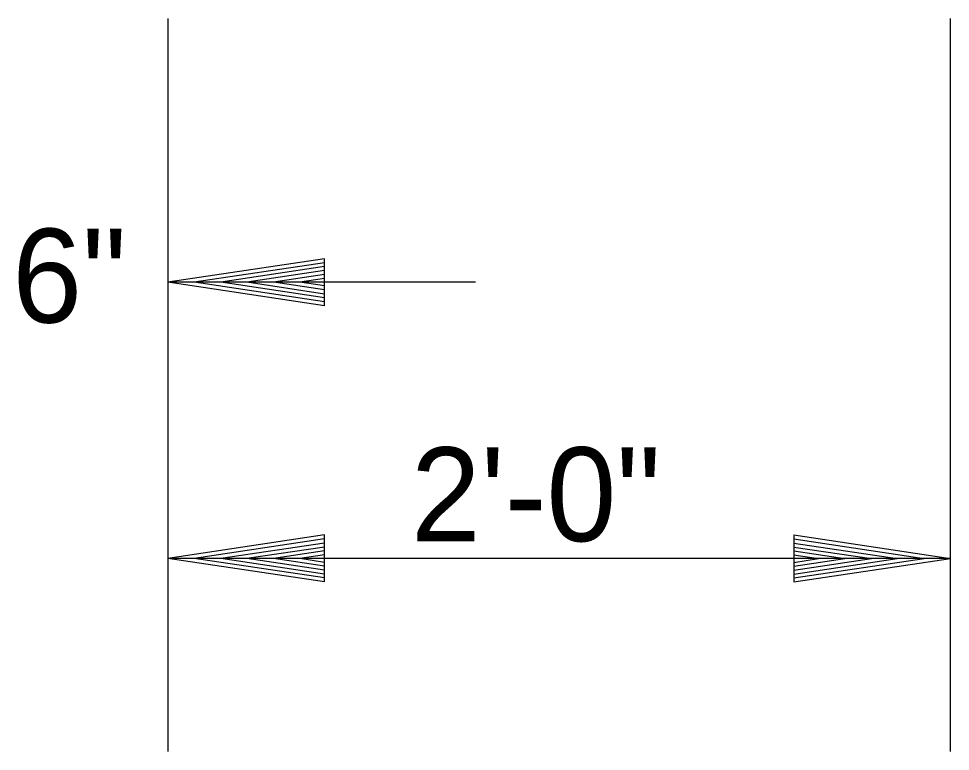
# Model space of a CAD drawing. Extents: x 635488 to 635865, y 290537 to 290973.
# Drawn here: x 635659.88 to 635665.84, y 290602.95 to 290607.63 of the extents above; entities that cross this region are included whole.
import ezdxf

# ---------------------------------------------------------------- set-up
doc = ezdxf.new("R2010")
doc.units = 0
doc.layers.add('Default', color=7, linetype='Continuous')

msp = doc.modelspace()

# ---------------------------------------------------------------- linework, layer by layer
at = {"layer": 'Default'}
for p, q in [((635660.8362, 290607.6342), (635660.8362, 290602.9506)), ((635665.8359, 290607.6342), (635665.8359, 290602.9506)), ((635661.8375, 290606.0988), (635660.8376, 290605.9488)), ((635661.8375, 290606.0738), (635661.0051, 290605.9488)), ((635661.8375, 290605.7988), (635661.8375, 290606.0988)), ((635661.8375, 290606.0488), (635661.1751, 290605.9488)), ((635661.8375, 290606.0238), (635661.3426, 290605.9488)), ((635661.8375, 290605.9988), (635661.5126, 290605.9488)), ((635662.8018, 290605.9497), (635660.8362, 290605.9497)), ((635661.8375, 290605.7988), (635660.8376, 290605.9488)), ((635661.8375, 290605.8238), (635661.0051, 290605.9488)), ((635661.8375, 290605.8488), (635661.1751, 290605.9488)), ((635661.8375, 290605.8738), (635661.3426, 290605.9488)), ((635661.8375, 290605.9013), (635661.5126, 290605.9488)), ((635661.8375, 290605.9738), (635661.6801, 290605.9488)), ((635661.8375, 290605.9263), (635661.6801, 290605.9488)), ((635661.8375, 290604.3339), (635660.8376, 290604.1839)), ((635661.8375, 290604.0339), (635661.8375, 290604.3339)), ((635664.8374, 290604.3339), (635665.8373, 290604.1839)), ((635664.8374, 290604.3339), (635664.8374, 290604.0339)), ((635661.8375, 290604.3089), (635661.0051, 290604.1839)), ((635661.8375, 290604.2814), (635661.1751, 290604.1839)), ((635664.8374, 290604.3089), (635665.6698, 290604.1839)), ((635664.8374, 290604.2814), (635665.4973, 290604.1839)), ((635661.8375, 290604.2564), (635661.3426, 290604.1839)), ((635661.8375, 290604.2314), (635661.5126, 290604.1839)), ((635664.8374, 290604.2564), (635665.3323, 290604.1839)), ((635664.8374, 290604.2314), (635665.1623, 290604.1839)), ((635665.8359, 290604.183), (635660.8362, 290604.183)), ((635661.8375, 290604.0339), (635660.8376, 290604.1839)), ((635661.8375, 290604.0589), (635661.0051, 290604.1839)), ((635661.8375, 290604.0839), (635661.1751, 290604.1839)), ((635661.8375, 290604.1089), (635661.3426, 290604.1839)), ((635661.8375, 290604.1339), (635661.5126, 290604.1839)), ((635661.8375, 290604.2064), (635661.6801, 290604.1839)), ((635661.8375, 290604.1589), (635661.6801, 290604.1839)), ((635664.8374, 290604.2064), (635664.9948, 290604.1839)), ((635664.8374, 290604.0339), (635665.8373, 290604.1839)), ((635664.8374, 290604.1339), (635665.1623, 290604.1839)), ((635664.8374, 290604.0839), (635665.4973, 290604.1839)), ((635664.8374, 290604.0589), (635665.6698, 290604.1839)), ((635664.8374, 290604.1089), (635665.3323, 290604.1839)), ((635664.8374, 290604.1589), (635664.9948, 290604.1839))]:
    msp.add_line(p, q, dxfattribs=at)

# ---------------------------------------------------------------- texts
for s, p in [('6"', (635659.8427, 290605.6913)), ('2\'-0"', (635662.39, 290604.2939))]:
    msp.add_text(s, height=0.6, dxfattribs=at).set_placement(p)

doc.saveas('drawing.dxf')
